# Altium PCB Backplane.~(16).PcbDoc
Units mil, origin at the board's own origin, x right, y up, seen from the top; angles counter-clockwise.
Board outline 6520 x 1500 mil, 6 copper layers (Top Layer, DGND, +5V, AGND, VCC, Bottom Layer), stack 50.76 mil thick; 22 components, 84 nets, 235 pads, 7 vias.
Unrouted connection lines stored in the file: 53.
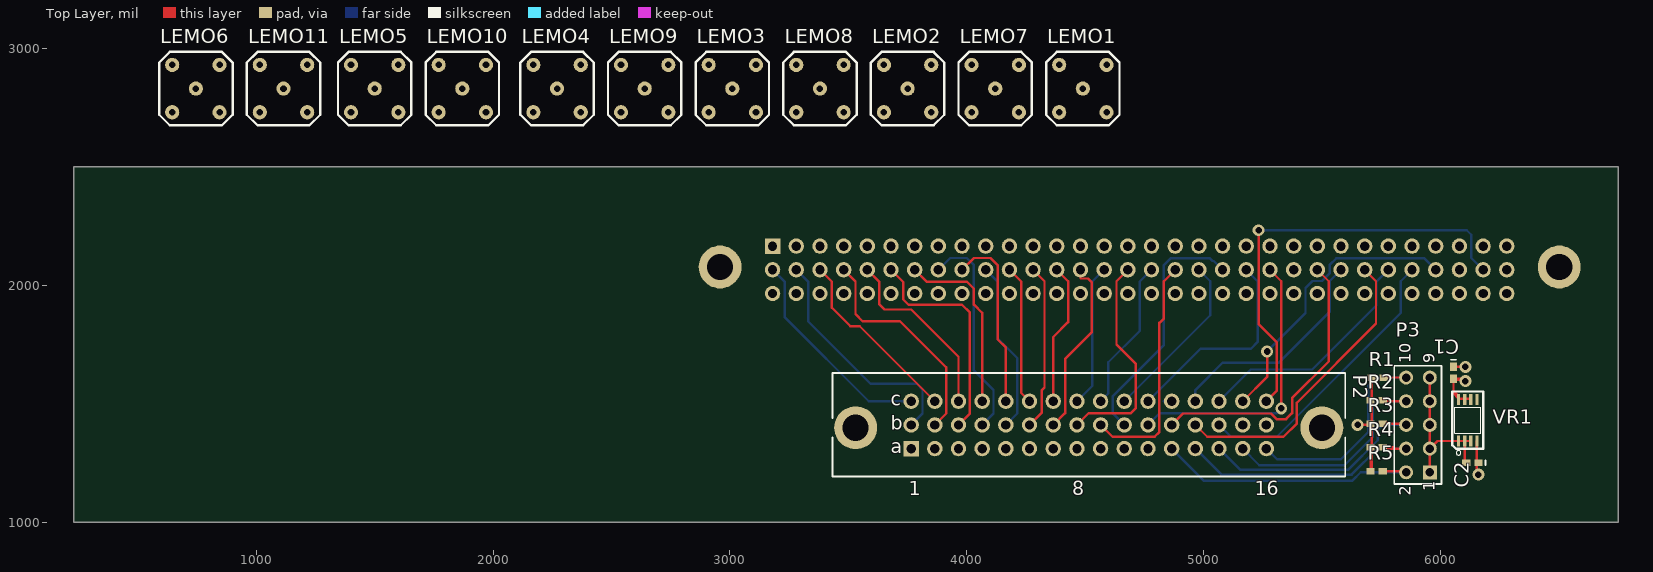
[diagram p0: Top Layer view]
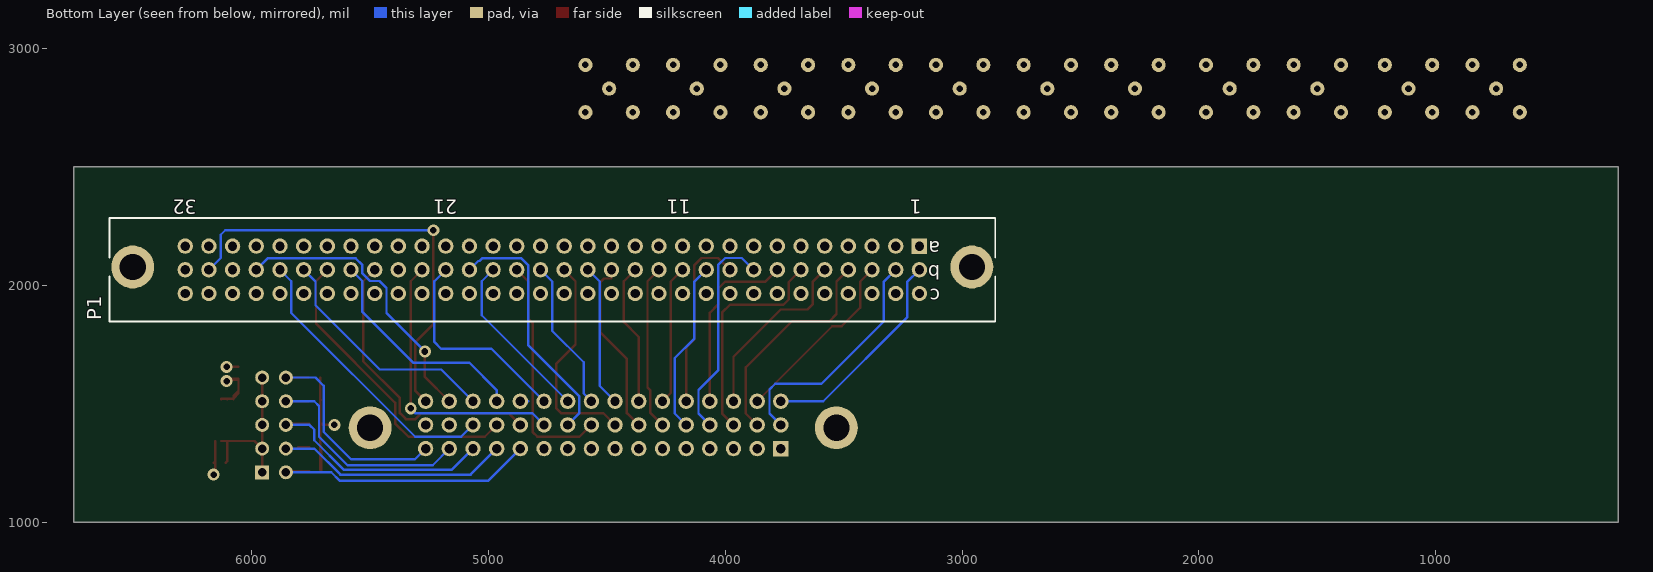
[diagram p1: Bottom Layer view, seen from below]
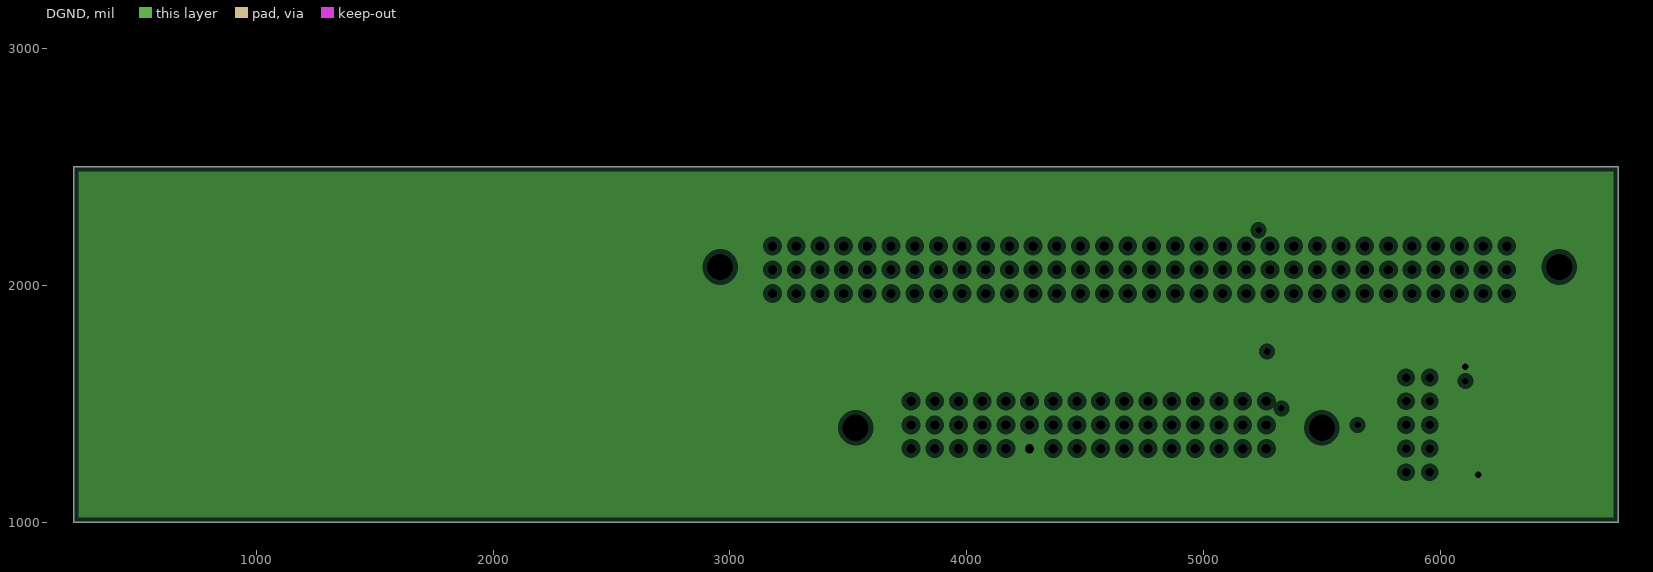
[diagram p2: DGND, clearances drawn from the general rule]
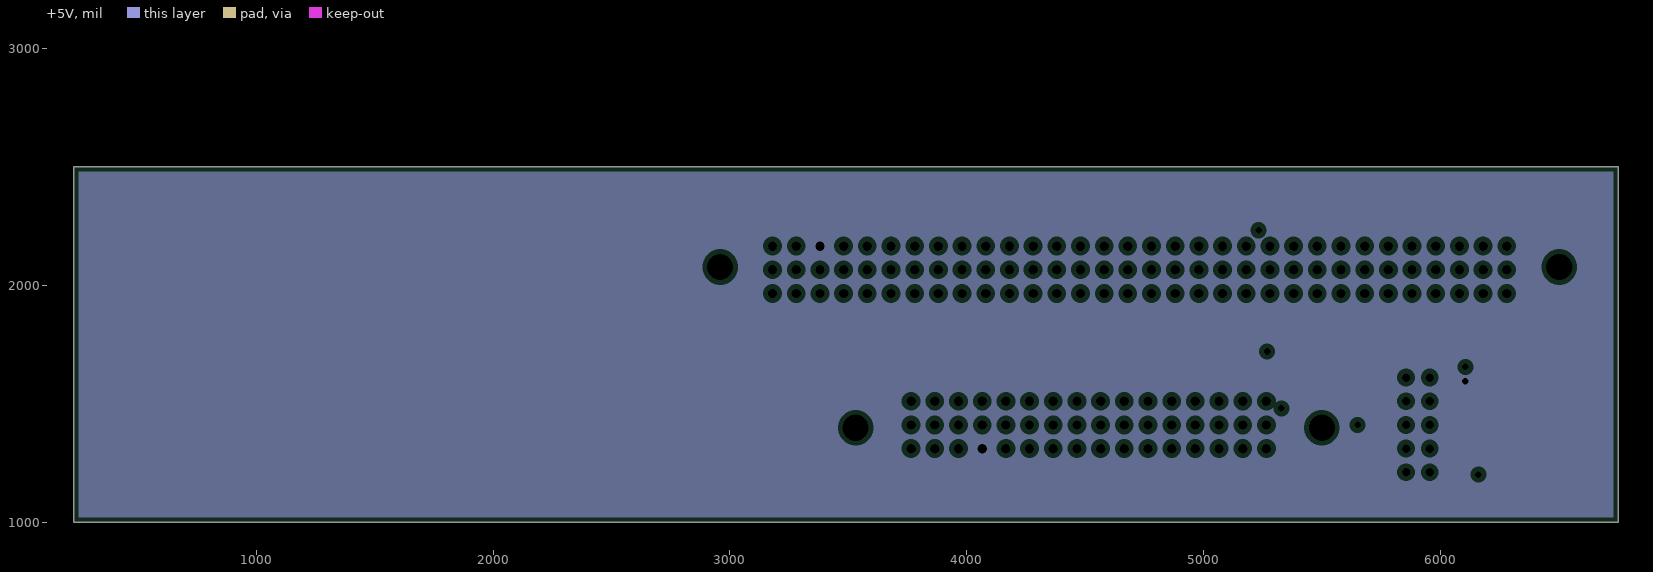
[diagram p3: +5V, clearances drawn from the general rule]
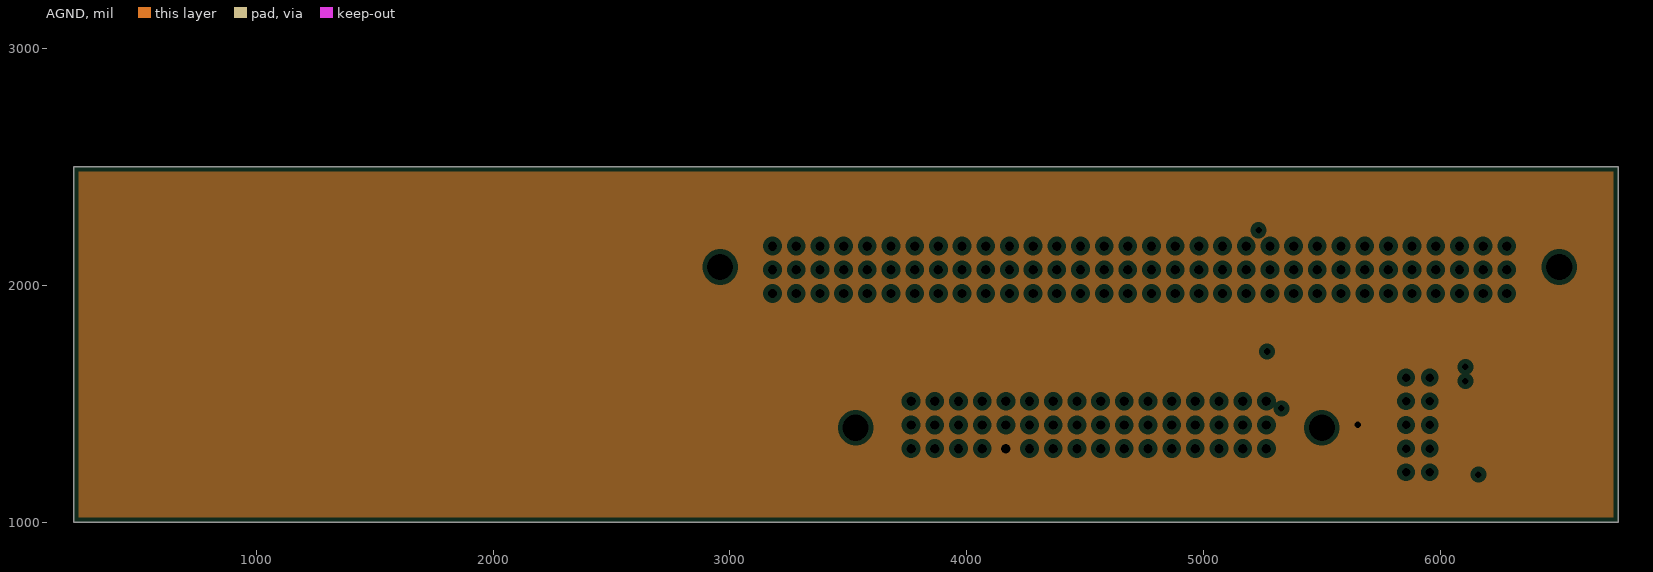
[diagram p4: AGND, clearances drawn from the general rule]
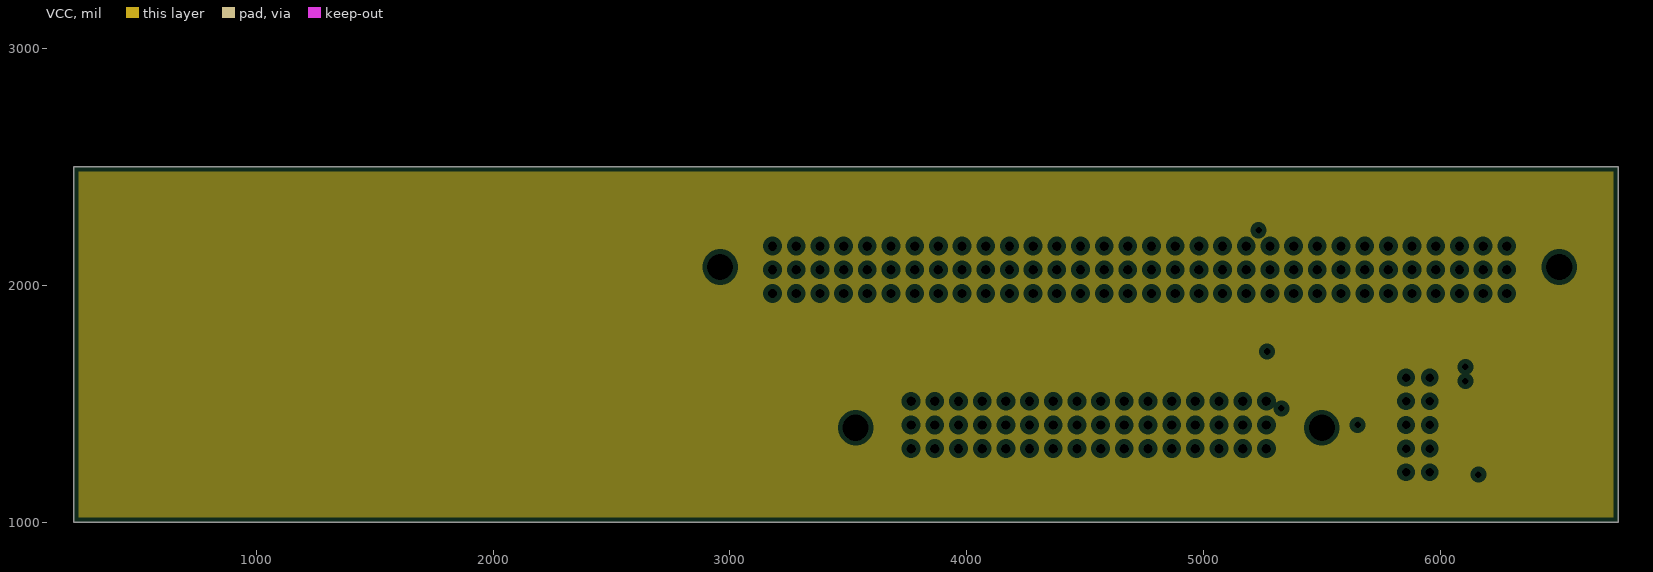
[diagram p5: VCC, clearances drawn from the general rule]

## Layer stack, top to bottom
Top Layer: signal copper 1.4
Dielectric: prepreg 5.1, FR-4, Dk 4.8
DGND: plane copper 1.4, net DGND
Dielectric: core 10.72, FR-4, Dk 4.8
+5V: plane copper 1.4, net +5V
Dielectric: prepreg 10.72, FR-4, Dk 4.8
AGND: plane copper 1.4, net AGND
Dielectric: core 10.72, FR-4, Dk 4.8
VCC: plane copper 1.4
Dielectric: prepreg 5.1, FR-4, Dk 4.8
Bottom Layer: signal copper 1.4

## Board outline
230,1000 6750,1000 6750,2500 230,2500

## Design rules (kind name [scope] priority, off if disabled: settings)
Clearance [All] p1: gap=10
ComponentClearance [All] p1: gap=10 collisioncheckmode=3 verticalgap=10
PlaneClearance [All] p1: clearance=20
PlaneConnect [All] p1: planeconnectstyle=Relief reliefexpansion=20 reliefentries=4 reliefconductorwidth=10 reliefairgap=10
PolygonConnect [All] p1: connectstyle=Relief reliefconductorwidth=10 reliefentries=4 polygonreliefangle="90 Angle"
RoomDefinition LEMO [InComponentClass('LEMO')] p1: confinementstyle=ConfineIn formatcopy=TRUE lockcomponents=FALSE outline 580,2665 4655,2665 4655,3100 580,3100
RoomDefinition "Digital Connector" [InComponentClass('Digital Connector')] p2: confinementstyle=ConfineIn formatcopy=TRUE lockcomponents=FALSE outline 3170,1085 6595,1085 6595,1895 3170,1895
RoomDefinition "Analog Connector" [InComponentClass('Analog Connector')] p3: confinementstyle=ConfineIn formatcopy=TRUE lockcomponents=FALSE outline 2650,1745 6670,1745 6670,2420 2650,2420
RoutingVias [All] p1: holewidth=28 width=50 viastyle="Through Hole" minholewidth=28 minwidth=50 maxholewidth=28 maxwidth=50
SolderMaskExpansion [All] p1: expansion=4
SupplyNets VCC [OnLayer('VCC')] p1: voltage=10.00
SupplyNets +5V [OnLayer('+5V')] p2: voltage=5.000
SupplyNets DGND [OnLayer(DGND)] p3: voltage=0.000
SupplyNets AGND [OnLayer('AGND')] p4: voltage=0.000
TestPointUsage [All] p1: valid=0 allowmultiple=FALSE
Testpoint [All] p1: side=15 testpointundercomponent=TRUE minsize=40 maxsize=100 preferedsize=60 minholesize=0 maxholesize=40 preferedholesize=32 testpointgrid=1 style=1023 order=0123456789
Width [All] p1: maxlimit=7.35 minlimit=2.1 preferedwidth=7.35 impedancedriven=TRUE minimp=50.000000 maximp=80.000000 favimp=50.000000
16 further rules are at their usual default settings.

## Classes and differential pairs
net class BIAS: SIPMBIAS1 SIPMBIAS2 SIPMBIAS3 SIPMBIAS4 SIPMBIAS5 SIPMBIAS6 SIPMBIAS7 SIPMBIAS8 SIPMBIAS9 SIPMBIAS10 SIPMBIAS11 SIPMBIAS12 SIPMBIAS13 SIPMBIAS14 SIPMBIAS15 SIPMBIAS16 SIPMBIAS17 SIPMBIAS18 SIPMBIAS19 SIPMBIAS20 SIPMBIAS21 SIPMBIAS22 SIPMBIAS23 SIPMBIAS24 SIPMBIAS25 SIPMBIAS26 SIPMBIAS27 SIPMBIAS28 SIPMBIAS29 SIPMBIAS30 SIPMBIAS31 SIPMBIAS32
component class LEMO: LEMO1 LEMO2 LEMO3 LEMO4 LEMO5 LEMO6 LEMO7 LEMO8 LEMO9 LEMO10 LEMO11
component class "Digital Connector": C1 C2 P2 P3 R1 R2 R3 R4 R5 R? VR1
component class "Analog Connector": P1

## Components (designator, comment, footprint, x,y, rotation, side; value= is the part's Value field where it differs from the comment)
C1 "Kemet C0402C104K8PACTU" 0402 6055,1630 r270 top
C2 "Kemet C1206C106K9PACTU" 0402 6135,1250 r180 top
LEMO1 "LEMO EPA.00" "LEMO EPA.00" 4490,2830 r0 top
LEMO2 "LEMO EPA.00" "LEMO EPA.00" 3750,2830 r0 top
LEMO3 "LEMO EPA.00" "LEMO EPA.00" 3010,2830 r0 top
LEMO4 "LEMO EPA.00" "LEMO EPA.00" 2270,2830 r0 top
LEMO5 "LEMO EPA.00" "LEMO EPA.00" 1500,2830 r0 top
LEMO6 "LEMO EPA.00" "LEMO EPA.00" 745,2830 r0 top
LEMO7 "LEMO EPA.00" "LEMO EPA.00" 4120,2830 r0 top
LEMO8 "LEMO EPA.00" "LEMO EPA.00" 3380,2830 r0 top
LEMO9 "LEMO EPA.00" "LEMO EPA.00" 2640,2830 r0 top
LEMO10 "LEMO EPA.00" "LEMO EPA.00" 1870,2830 r0 top
LEMO11 "LEMO EPA.00" "LEMO EPA.00" 1115,2830 r0 top
P1 "DIN41612 96 pin, Backplane" EURO2.54-2V96 4730,2065 r0 bottom
P2 "DIN41612 48 pin, Backplane" EURO2.54-2V48 4515,1410 r0 top
P3 "Header 5X2" HDR2X5 5955,1210 r90 top
R1 "Res2" 1005[0402] 5735,1610 r0 top
R2 "Res2" 1005[0402] 5730,1515 r0 top
R3 "Res2" 1005[0402] 5730,1415 r0 top
R4 "Res2" 1005[0402] 5730,1315 r0 top
R5 "Res2" 1005[0402] 5730,1215 r0 top
VR1 "" RM-8 6115,1430 r0 top

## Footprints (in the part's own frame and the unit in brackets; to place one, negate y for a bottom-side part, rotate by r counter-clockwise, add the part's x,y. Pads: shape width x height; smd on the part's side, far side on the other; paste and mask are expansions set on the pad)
0402 [mm] "Chip Capacitor; Body 1.0 x 0.5 mm (LxW typ)"
  rect 0.9x0.7 smd: 1(-0.65,0) 2(0.65,0)
  silkscreen extent -1.4,-0.25 -1.4,0.25
1005[0402] [mm] "Chip Resistor; Body 1.1 x 0.5 mm (LxW typ)"
  rect 0.9x0.7 smd: 1(-0.65,0) 2(0.65,0)
EURO2.54-2V48 [mm] "Connector; DIN 41612, Type 2C, Thru-Hole; Rows a+b+c, 48 Position; Vertical"
  round 4.6 hole 2.8: 17(-25,-0.3) 18(25,-0.3)
  rect 1.65x1.65 hole 1: A1(-19.05,-2.54)
  round 1.65 hole 1: A2(-16.51,-2.54) A3(-13.97,-2.54) A4(-11.43,-2.54) A5(-8.89,-2.54) A6(-6.35,-2.54) A7(-3.81,-2.54) A8(-1.27,-2.54) A9(1.27,-2.54) A10(3.81,-2.54) A11(6.35,-2.54) A12(8.89,-2.54) A13(11.43,-2.54) A14(13.97,-2.54) A15(16.51,-2.54) A16(19.05,-2.54) B1(-19.05,0) B2(-16.51,0) B3(-13.97,0) B4(-11.43,0) B5(-8.89,0) B6(-6.35,0) B7(-3.81,0) B8(-1.27,0) B9(1.27,0) B10(3.81,0) B11(6.35,0) B12(8.89,0) B13(11.43,0) B14(13.97,0) B15(16.51,0) B16(19.05,0) C1(-19.05,2.54) C2(-16.51,2.54) C3(-13.97,2.54) C4(-11.43,2.54) C5(-8.89,2.54) C6(-6.35,2.54) C7(-3.81,2.54) C8(-1.27,2.54) C9(1.27,2.54) C10(3.81,2.54) C11(6.35,2.54) C12(8.89,2.54) C13(11.43,2.54) C14(13.97,2.54) C15(16.51,2.54) C16(19.05,2.54)
  silkscreen extent -27.5,-5.55 27.5,5.55
EURO2.54-2V96 [mm] "Connector; DIN 41612, Type C, Thru-Hole; Rows a+b+c, 96 Position; Vertical"
  round 4.6 hole 2.8: 33(-45,-0.3) 34(45,-0.3)
  rect 1.65x1.65 hole 1: A1(-39.37,-2.54)
  round 1.65 hole 1: A2(-36.83,-2.54) A3(-34.29,-2.54) A4(-31.75,-2.54) A5(-29.21,-2.54) A6(-26.67,-2.54) A7(-24.13,-2.54) A8(-21.59,-2.54) A9(-19.05,-2.54) A10(-16.51,-2.54) A11(-13.97,-2.54) A12(-11.43,-2.54) A13(-8.89,-2.54) A14(-6.35,-2.54) A15(-3.81,-2.54) A16(-1.27,-2.54) A17(1.27,-2.54) A18(3.81,-2.54) A19(6.35,-2.54) A20(8.89,-2.54) A21(11.43,-2.54) A22(13.97,-2.54) A23(16.51,-2.54) A24(19.05,-2.54) A25(21.59,-2.54) A26(24.13,-2.54) A27(26.67,-2.54) A28(29.21,-2.54) A29(31.75,-2.54) A30(34.29,-2.54) A31(36.83,-2.54) A32(39.37,-2.54) B1(-39.37,0) B2(-36.83,0) B3(-34.29,0) B4(-31.75,0) B5(-29.21,0) B6(-26.67,0) B7(-24.13,0) B8(-21.59,0) B9(-19.05,0) B10(-16.51,0) B11(-13.97,0) B12(-11.43,0) B13(-8.89,0) B14(-6.35,0) B15(-3.81,0) B16(-1.27,0) B17(1.27,0) B18(3.81,0) B19(6.35,0) B20(8.89,0) B21(11.43,0) B22(13.97,0) B23(16.51,0) B24(19.05,0) B25(21.59,0) B26(24.13,0) B27(26.67,0) B28(29.21,0) B29(31.75,0) B30(34.29,0) B31(36.83,0) B32(39.37,0) C1(-39.37,2.54) C2(-36.83,2.54) C3(-34.29,2.54) C4(-31.75,2.54) C5(-29.21,2.54) C6(-26.67,2.54) C7(-24.13,2.54) C8(-21.59,2.54) C9(-19.05,2.54) C10(-16.51,2.54) C11(-13.97,2.54) C12(-11.43,2.54) C13(-8.89,2.54) C14(-6.35,2.54) C15(-3.81,2.54) C16(-1.27,2.54) C17(1.27,2.54) C18(3.81,2.54) C19(6.35,2.54) C20(8.89,2.54) C21(11.43,2.54) C22(13.97,2.54) C23(16.51,2.54) C24(19.05,2.54) C25(21.59,2.54) C26(24.13,2.54) C27(26.67,2.54) C28(29.21,2.54) C29(31.75,2.54) C30(34.29,2.54) C31(36.83,2.54) C32(39.37,2.54)
  silkscreen extent -47.5,-5.55 47.5,5.55
HDR2X5 [mm] "Connector; Header; 5x2 Position"
  rect 1.5x1.5 hole 0.9: 1(0,0)
  round 1.5 hole 0.9: 2(0,2.54) 3(2.54,0) 4(2.54,2.54) 5(5.08,0) 6(5.08,2.54) 7(7.62,0) 8(7.62,2.54) 9(10.16,0) 10(10.16,2.54)
  silkscreen extent -1.27,-1.27 11.43,3.81
"LEMO EPA.00" [mil]
  round 60 hole 27.56: 0(0,0) 1(-100,100) 2(100,100) 3(100,-100) 4(-100,-100)
  silkscreen extent -155,-155 155,155
RM-8 [mil]
  rect 13.4x46.9 smd: 1(-38.6,-87.8) 2(-12.6,-87.8) 3(12.6,-87.8) 4(38.6,-87.8) 5(38.6,87.8) 6(12.6,87.8) 7(-12.6,87.8) 8(-38.6,87.8)
  silkscreen extent -65,-148 65,121

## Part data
C1 C2: library part Cap, "Capacitor"
P3: "Header, 5-Pin, Dual row"
R1 R2 R3 R4 R5: "Resistor"
VR1: library part ADP3335

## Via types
v1: diameter 50, hole 28, Top Layer to Bottom Layer, 7 vias

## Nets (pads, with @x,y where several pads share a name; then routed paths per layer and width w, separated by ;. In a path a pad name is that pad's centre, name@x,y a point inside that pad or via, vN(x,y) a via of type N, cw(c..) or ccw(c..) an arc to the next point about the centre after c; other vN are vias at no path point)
+3.3V: C2.2 P3.1 P3.3 P3.5 P3.7 P3.9 VR1.1 VR1.2 VR1.3 | length 681
  Top Layer w10: P3.1 P3.3 ; P3.9 P3.7 P3.5 P3.3 ; C2.2 6102.4,1257.01 VR1.2 ; VR1.3 VR1.2 ; P3.3 5987.2,1342.2 VR1.1 VR1.2
+5V: C1.2 P1.A3 P2.A4 VR1.6 VR1.7 VR1.8 | length 333.9
  Top Layer w10: VR1.8 VR1.8@6076.4,1521 ; VR1.7 VR1.7@6102.4,1520 ; v1(6105,1595) v1@6100,1600 ; v1@6115,1600 6105,1600 v1@6100,1600 ; VR1.6 6127.6,1520 VR1.7@6102.4,1520 ; 6055,1554.4 C1.2@6055,1600 ; 6055,1554.4 6055,1543.6 VR1.8@6076.4,1522.2 ; 6055,1554.4 6076.4,1533 VR1.8@6076.4,1522.2 ; C1.2@6055,1600 C1.2 6095.59,1604.41 v1@6100,1600 ; C1.2@6055,1600 v1@6100,1600 ; VR1.8@6076.4,1521 VR1.8@6076.4,1522.2 ; VR1.8@6076.4,1521 VR1.8@6077.6,1521 ; VR1.8@6076.4,1522.2 VR1.8@6077.6,1521 ; VR1.8@6077.6,1521 6102.4,1521 VR1.7@6102.4,1520 ; VR1.8@6077.6,1521 6078.6,1520 VR1.7@6102.4,1520
+210V: P2.A2
-5V: P2.A3
ADC_EXT1: P2.A7
ADC_EXT2: P2.A8
AGND: LEMO1.1 LEMO1.2 LEMO1.3 LEMO1.4 LEMO2.1 LEMO2.2 LEMO2.3 LEMO2.4 LEMO3.1 LEMO3.2 LEMO3.3 LEMO3.4 LEMO4.1 LEMO4.2 LEMO4.3 LEMO4.4 LEMO5.1 LEMO5.2 LEMO5.3 LEMO5.4 LEMO6.1 LEMO6.2 LEMO6.3 LEMO6.4 LEMO7.1 LEMO7.2 LEMO7.3 LEMO7.4 LEMO8.1 LEMO8.2 LEMO8.3 LEMO8.4 LEMO9.1 LEMO9.2 LEMO9.3 LEMO9.4 LEMO10.1 LEMO10.2 LEMO10.3 LEMO10.4 LEMO11.1 LEMO11.2 LEMO11.3 LEMO11.4 P2.A5 R1.1 R2.1 R3.1 R4.1 R5.1 | length 664.6
  Top Layer w10: v1(5650,1410) 5699.41,1410 5699.41,1415 R3.1 5709,1415 R2.1@5709,1515 ; R5.1 5705,1215 R4.1@5705,1315 ; R4.1 R4.1@5705,1315 ; R2.1 R2.1@5709,1515 ; R5.1@5709.41,1220 R4.1@5709.41,1315 ; R1.1 R2.1@5709.41,1515 ; R4.1@5705,1315 R4.1@5709.41,1315 ; R2.1@5709,1515 R2.1@5709.41,1515 ; R4.1@5709.41,1315 5709.41,1415 R2.1@5709.41,1515
CP2201/LA: P2.A1
DGND: C1.1 C2.1 P2.A6 VR1.4 | length 202.1
  Top Layer w10: C1.1 6104.41,1655.59 v1(6105,1655) ; VR1.4 C2.1@6153.6,1250 ; v1(6160,1200) 6153.6,1206.4 C2.1@6153.6,1250 ; C2.1 C2.1@6153.6,1250
ID0: P2.A16 P3.10 R1.2 | length 960.2
  Top Layer w10: R1.2 P3.10
  Bottom Layer w10: P2.A16 5310,1265 5580,1265 5695,1380 5695,1575 5730,1610 P3.10
ID1: P2.A15 P3.8 R2.2 | length 1001.4
  Top Layer w10: R2.2@5760.59,1510 P3.8
  Bottom Layer w10: P2.A15 5235,1240 5595,1240 5715,1360 5715,1490 5735,1510 P3.8
ID2: P2.A14 P3.6 R3.2 | length 1036.8
  Top Layer w10: R3.2 5855,1415 P3.6
  Bottom Layer w10: P2.A14 5155,1220 5610,1220 5735,1345 5735,1390 5755,1410 P3.6
ID3: P2.A13 P3.4 R4.2 | length 1129
  Top Layer w10: R4.2 5802,1315 5807,1310 ; R4.2@5760.59,1310 5807,1310 ; P3.4 5807,1310
  Bottom Layer w10: P2.A13 5075,1200 5625,1200 5735,1310 P3.4
ID4: P2.A12 P3.2 R5.2 | length 1164.8
  Top Layer w10: R5.2 5855,1215 P3.2
  Bottom Layer w10: P2.A12 5000,1175 5628.28,1175 5663.28,1210 P3.2
SIPMBIAS1: P1.B1 P2.C1 | length 902.2
  Bottom Layer w10: P1.B1 3232,2013 3232,1864 3586,1510 P2.C1
SIPMBIAS2: P1.B2 P2.B1 | length 1009.9
  Bottom Layer w10: P1.B2 3330,2015 3330,1848 3594,1584 3789,1584 3813,1560 3813,1458 P2.B1
SIPMBIAS3: P1.B3 P2.C2 | length 779.2
  Top Layer w10: P1.B3 3430,2015 3430,1905.24 3508.57,1826.67 3548.33,1826.67 P2.C2
SIPMBIAS4: P1.B4 P2.B2 | length 946.8
  Top Layer w10: P1.B4 3530,2015 3530,1878 3560,1848 3718,1848 3913,1653 3913,1458 P2.B2
SIPMBIAS5: P1.B5 P2.C3 | length 780.7
  Top Layer w10: P1.B5 3630,2015 3630,1920 3652.48,1897.52 3765.48,1897.52 3965,1698 P2.C3
SIPMBIAS6: P1.B6 P2.B3 | length 944.9
  Top Layer w10: P1.B6 3732,2013 3732,1940 3754.48,1917.52 3980,1917.52 4013,1884.52 4013,1458 P2.B3
SIPMBIAS7: P1.B7 P2.C4 | length 772.6
  Top Layer w10: P1.B7 3830,2015 4000,2015 4030,1985 4030,1918 4065,1883 P2.C4
SIPMBIAS8: P1.B8 P2.B4 | length 912.4
  Bottom Layer w10: P1.B8 3930,2115 4000,2115 4030,2085 4030,1640 4113,1557 4113,1458 P2.B4
SIPMBIAS9: P1.B9 P2.C5 | length 772.6
  Top Layer w10: P1.B9 4030,2115 4100,2115 4130,2085 4130,1772 4165,1737 P2.C5
SIPMBIAS10: P1.B10 P2.B5 | length 730
  Bottom Layer w10: P1.B10 4130,2015 4130,1775 4213,1692 4213,1458 P2.B5
SIPMBIAS11: P1.B11 P2.C6 | length 590.2
  Top Layer w10: P1.B11 4230,2015 4230,1545 P2.C6
SIPMBIAS12: P1.B12 P2.B6 | length 701
  Top Layer w10: P2.B6 4317,1462 4317,1557 4328,1568 4328,2017 P1.B12
SIPMBIAS13: P1.B13 P2.C7 | length 601
  Top Layer w10: P2.C7 4365,1781 4428,1844 4428,2017 P1.B13
SIPMBIAS14: P1.B14 P2.B7 | length 761.1
  Top Layer w10: P2.B7 4415,1460 4415,1689 4528,1802 4528,2012 4512,2028 4480,2028 P1.B14
SIPMBIAS15: P1.B15 P2.C8 | length 602.6
  Bottom Layer w10: P2.C8 4530,1575 4530,2015 P1.B15
SIPMBIAS16: P1.B16 P2.B8 | length 915.4
  Top Layer w10: P2.B8 4515,1460 4693,1460 4713,1480 4713,1669 4632,1750 4632,2017 P1.B16
SIPMBIAS17: P1.B17 P2.C9 | length 644.1
  Bottom Layer w10: P2.C9 4597.52,1542.52 4597.52,1674.44 4730,1806.92 4730,2015 P1.B17
SIPMBIAS18: P1.B18 P2.B9 | length 989.7
  Top Layer w10: P2.B9 4615,1360 4793,1360 4813,1380 4813,1841 4832,1860 4832,2017 P1.B18
SIPMBIAS19: P1.B19 P2.C10 | length 725.2
  Bottom Layer w10: P2.C10 5028,1873 5028,2017 P1.B19
SIPMBIAS20: P1.B20 P2.B10 | length 1063.4
  Bottom Layer w10: P2.B10 4617,1458 4617,1531.93 4832,1746.93 4832,2085 4860,2113 5027,2113 5038,2102 5043,2102 P1.B20
SIPMBIAS21: P1.B21 P2.C11 | length 891.4
  Bottom Layer w10: P2.C11 4987,1732 5200,1732 5228,1760 5228,2017 P1.B21
SIPMBIAS22: P1.B22 P2.B11 | length 1196.9
  Top Layer w10: P1.B22 5328,2017 v1(5328,1480)
  Bottom Layer w10: P2.B11 4815,1460 5308,1460 v1(5328,1480)
SIPMBIAS23: P1.B23 P2.C12 | length 32.9
  Bottom Layer w10: 4832.15,1510 P2.C12
SIPMBIAS24: P1.B24 P2.B12 | length 1237.5
  Top Layer w10: P2.B12 4913,1458 5284.15,1458 5307.45,1434.7 5348.4,1434.7 5373.7,1460 5373.7,1523.74 5528,1678.04 5528,2017 P1.B24
SIPMBIAS25: P1.B25 P2.C13 | length 948.6
  Bottom Layer w10: P2.C13 4965,1557 5081,1673 5318,1673 5532,1887 5532,2017 P1.B25
SIPMBIAS26: P1.B26 P2.B13 | length 1279.8
  Top Layer w10: P2.B13 5015,1360 5337.38,1360 5393.7,1416.32 5393.7,1503.74 5728,1838.04 5728,2017 P1.B26
SIPMBIAS27: P1.B27 P2.C14 | length 1003.5
  Bottom Layer w10: P2.C14 5199,1644 5459,1644 5730,1915 5730,2015 P1.B27
SIPMBIAS28: P1.B28 P2.B14 | length 1206.2
  Bottom Layer w10: P2.B14 5115,1360 5309,1360 5832,1883 5832,2017 P1.B28
SIPMBIAS29: P1.B29 P2.C15 | length 1229.7
  Top Layer w10: P2.C15 5268,1613 v1(5268,1720)
  Bottom Layer w10: v1(5268,1720) 5430,1882 5430,1987.52 5460,2017.52 5499.67,2017.52 5532,2049.85 5532,2085 5560,2113 5932,2113 P1.B29
SIPMBIAS30: P1.B30 P2.B15
SIPMBIAS31: P1.B31 P2.C16 | length 1845.9
  Top Layer w10: v1(5232,2232) 5232,1836 5308,1760 5308,1553 P2.C16
  Bottom Layer w10: v1(5232,2232) 6111,2232 6130,2213 6130,2115 P1.B31
SIPMBIAS32: P1.B32 P2.B16
SIPMOUT1: P1.C1
SIPMOUT2: P1.C2
SIPMOUT3: P1.C3
SIPMOUT4: P1.C4
SIPMOUT5: P1.C5
SIPMOUT6: P1.C6
SIPMOUT7: P1.C7
SIPMOUT8: P1.C8
SIPMOUT9: P1.C9
SIPMOUT10: P1.C10
SIPMOUT11: P1.C11
SIPMOUT12: P1.C12
SIPMOUT13: P1.C13
SIPMOUT14: P1.C14
SIPMOUT15: P1.C15
SIPMOUT16: P1.C16
SIPMOUT17: P1.C17
SIPMOUT18: P1.C18
SIPMOUT19: P1.C19
SIPMOUT20: P1.C20
SIPMOUT21: P1.C21
SIPMOUT22: P1.C22
SIPMOUT23: P1.C23
SIPMOUT24: P1.C24
SIPMOUT25: P1.C25
SIPMOUT26: P1.C26
SIPMOUT27: P1.C27
SIPMOUT28: P1.C28
SIPMOUT29: P1.C29
SIPMOUT30: P1.C30
SIPMOUT31: P1.C31
SIPMOUT32: P1.C32
SUMMED1: LEMO1.0 LEMO6.0 P1.A1
SUMMED2: LEMO2.0 P1.A6
SUMMED3: LEMO3.0 P1.A11
SUMMED4: LEMO4.0 P1.A16
SUMMED5: LEMO5.0 P1.A21
SUMMED6: P1.A26
pads on no net: LEMO7.0 LEMO8.0 LEMO9.0 LEMO10.0 LEMO11.0 P1.33 P1.34 P1.A2 P1.A4 P1.A5 P1.A7 P1.A8 P1.A9 P1.A10 P1.A12 P1.A13 P1.A14 P1.A15 P1.A17 P1.A18 P1.A19 P1.A20 P1.A22 P1.A23 P1.A24 P1.A25 P1.A27 P1.A28 P1.A29 P1.A30 P1.A31 P1.A32 P2.17 P2.18 P2.A9 P2.A10 P2.A11 VR1.5

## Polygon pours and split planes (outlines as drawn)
DGND on DGND (split plane): 6729.61,1020.39 250.39,1020.39 250.39,2479.61 6729.61,2479.61
AGND on AGND (split plane): 6729.61,1020.39 250.39,1020.39 250.39,2479.61 6729.61,2479.61
+5V on +5V (split plane): 6729.61,1020.39 250.39,1020.39 250.39,2479.61 6729.61,2479.61
no net on VCC (split plane): 6729.61,1020.39 250.39,1020.39 250.39,2479.61 6729.61,2479.61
